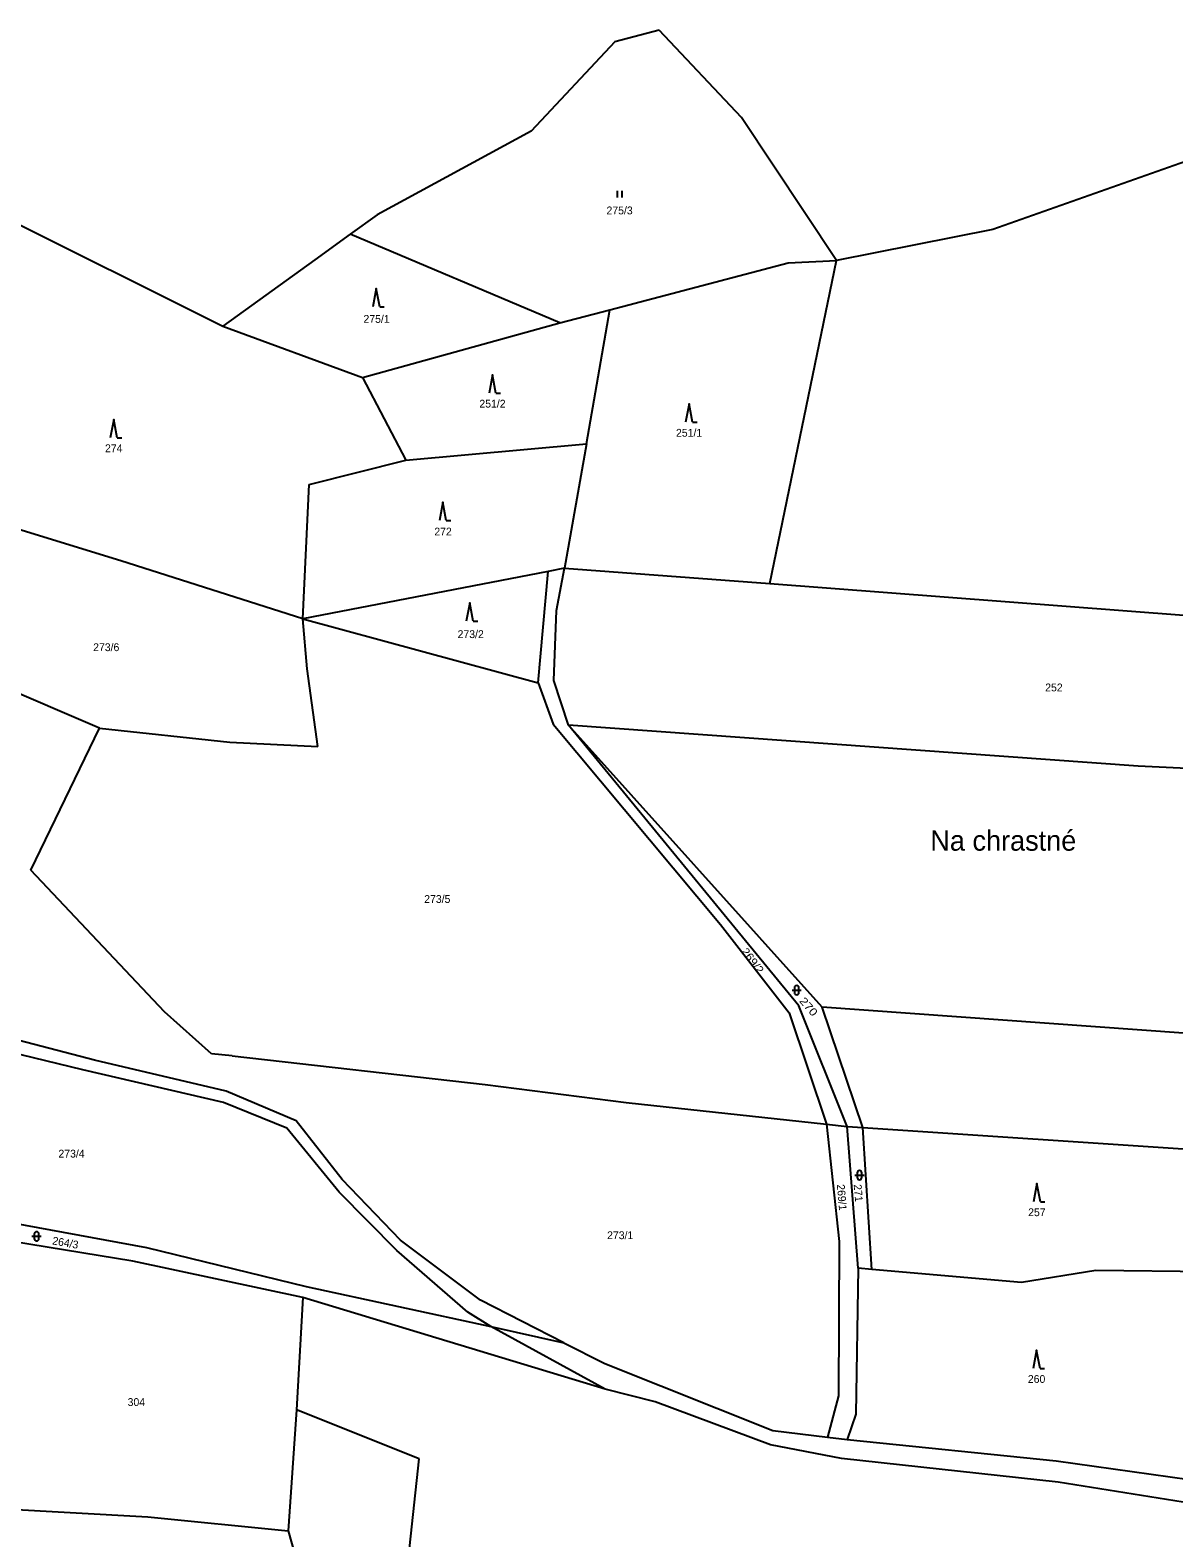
# Model space of a CAD drawing. Extents: x -791548 to -789311, y -1142631 to -1140855.
# Drawn here: x -791099.4 to -790850.9, y -1141698.3 to -1141370.5 of the extents above; entities that cross this region are included whole.
import ezdxf
from ezdxf.enums import TextEntityAlignment as Align

# ---------------------------------------------------------------- set-up
doc = ezdxf.new("R2010")
doc.units = 0
doc.header["$LTSCALE"] = 0.68
for name, color, linetype, lineweight in [('1', 7, 'Continuous', 25), ('3', 7, 'Continuous', 25), ('7', 7, 'Continuous', 13)]:
    doc.layers.add(name, color=color, linetype=linetype, lineweight=lineweight)
doc.layers.add('2', color=7, linetype='Continuous')

msp = doc.modelspace()

# ---------------------------------------------------------------- linework, layer by layer
at = {"layer": '1'}
for p, q in [((-790962.75, -1141370.54), (-790972.33, -1141373.08)), ((-790944.86, -1141389.53), (-790962.75, -1141370.54)), ((-790972.33, -1141373.08), (-790990.5, -1141392.51)), ((-790924.22, -1141420.63), (-790944.86, -1141389.53)), ((-790990.5, -1141392.51), (-791023.99, -1141410.69)), ((-790837.35, -1141395.22), (-790890.23, -1141413.86)), ((-791108.44, -1141409.5), (-791057.55, -1141434.87)), ((-791023.99, -1141410.69), (-791029.84, -1141414.9)), ((-791029.84, -1141414.9), (-791037.53, -1141420.44)), ((-790984.3, -1141434.2), (-791029.84, -1141414.9)), ((-790890.23, -1141413.86), (-790924.22, -1141420.63)), ((-791037.53, -1141420.44), (-791057.55, -1141434.87)), ((-790973.42, -1141431.36), (-790934.7, -1141421.13)), ((-790938.64, -1141490.83), (-790924.22, -1141420.63)), ((-790934.7, -1141421.13), (-790924.22, -1141420.63)), ((-790984.3, -1141434.2), (-790973.42, -1141431.36)), ((-790978.5, -1141460.45), (-790973.42, -1141431.36)), ((-791057.55, -1141434.87), (-791027.17, -1141446.05)), ((-791027.17, -1141446.05), (-790984.3, -1141434.2)), ((-791027.17, -1141446.05), (-791017.79, -1141464.03)), ((-791017.79, -1141464.03), (-790978.5, -1141460.45)), ((-790978.5, -1141460.45), (-790983.27, -1141487.53)), ((-791038.76, -1141469.32), (-791017.79, -1141464.03)), ((-791079.72, -1141485.89), (-791128.04, -1141471.09)), ((-791040.13, -1141498.5), (-791038.76, -1141469.32)), ((-791040.13, -1141498.5), (-791079.72, -1141485.89)), ((-790986.85, -1141488.22), (-791040.13, -1141498.5)), ((-790989.03, -1141512.44), (-790986.85, -1141488.22)), ((-790983.27, -1141487.53), (-790986.85, -1141488.22)), ((-790985.02, -1141496.73), (-790983.27, -1141487.53)), ((-790983.27, -1141487.53), (-790938.64, -1141490.83)), ((-790938.64, -1141490.83), (-790848.75, -1141497.75)), ((-791039.18, -1141509.38), (-791040.13, -1141498.5)), ((-791040.13, -1141498.5), (-790989.03, -1141512.44)), ((-790985.61, -1141511.92), (-790985.02, -1141496.73)), ((-791084.34, -1141522.3), (-791110.48, -1141511.03)), ((-791036.9, -1141526.25), (-791039.18, -1141509.38)), ((-790989.03, -1141512.44), (-790985.77, -1141521.43)), ((-790982.45, -1141521.64), (-790985.61, -1141511.92)), ((-790985.77, -1141521.43), (-790949.41, -1141564.98)), ((-791099.25, -1141553.12), (-791084.34, -1141522.3)), ((-791084.34, -1141522.3), (-791056.04, -1141525.31)), ((-790858.67, -1141530.56), (-790982.45, -1141521.64)), ((-790950.88, -1141560.03), (-790982.45, -1141521.64)), ((-790927.3, -1141582.95), (-790982.45, -1141521.64)), ((-791056.04, -1141525.31), (-791036.9, -1141526.25)), ((-790765.51, -1141534.95), (-790858.67, -1141530.56)), ((-791070.2, -1141583.91), (-791099.25, -1141553.12)), ((-790932.34, -1141582.61), (-790950.88, -1141560.03)), ((-790949.41, -1141564.98), (-790934.49, -1141584.17)), ((-791085.44, -1141594.43), (-791129.12, -1141583.07)), ((-790921.84, -1141608.87), (-790932.34, -1141582.61)), ((-790848.8, -1141588.58), (-790927.3, -1141582.95)), ((-790918.49, -1141609.09), (-790927.3, -1141582.95)), ((-791059.96, -1141593.07), (-791070.2, -1141583.91)), ((-790934.49, -1141584.17), (-790926.36, -1141608.38)), ((-791087.93, -1141596.55), (-791115.96, -1141589.76)), ((-791055.52, -1141593.51), (-791059.96, -1141593.07)), ((-791055.52, -1141593.51), (-791000.56, -1141599.75)), ((-791057.35, -1141603.63), (-791087.93, -1141596.55)), ((-791056.77, -1141601.17), (-791085.44, -1141594.43)), ((-791000.56, -1141599.75), (-790969.86, -1141603.69)), ((-791041.62, -1141607.64), (-791056.77, -1141601.17)), ((-791043.59, -1141609.2), (-791057.35, -1141603.63)), ((-790969.86, -1141603.69), (-790926.36, -1141608.38)), ((-791032.23, -1141623.15), (-791043.59, -1141609.2)), ((-791031.59, -1141620.42), (-791041.62, -1141607.64)), ((-790926.36, -1141608.38), (-790923.63, -1141633.86)), ((-790926.36, -1141608.38), (-790921.84, -1141608.87)), ((-790919.46, -1141639.69), (-790921.84, -1141608.87)), ((-790921.84, -1141608.87), (-790918.49, -1141609.09)), ((-790916.53, -1141639.95), (-790918.49, -1141609.09)), ((-790918.49, -1141609.09), (-790843.22, -1141614.13)), ((-791018.96, -1141633.6), (-791031.59, -1141620.42)), ((-791019.72, -1141635.8), (-791032.23, -1141623.15)), ((-791114.69, -1141627.72), (-791074.08, -1141635.2)), ((-791077.08, -1141638.15), (-791107.99, -1141633.07)), ((-791074.08, -1141635.2), (-791039.43, -1141643.64)), ((-791004.31, -1141649.23), (-791019.72, -1141635.8)), ((-791001.54, -1141646.64), (-791018.96, -1141633.6)), ((-790923.63, -1141633.86), (-790923.78, -1141667.45)), ((-791040.18, -1141646.05), (-791077.08, -1141638.15)), ((-790919.46, -1141639.69), (-790920, -1141671.39)), ((-790916.53, -1141639.95), (-790919.46, -1141639.69)), ((-790884, -1141642.79), (-790916.53, -1141639.95)), ((-790867.82, -1141640.21), (-790884, -1141642.79)), ((-790841.97, -1141640.5), (-790867.82, -1141640.21)), ((-791039.43, -1141643.64), (-790999.3, -1141652.37)), ((-791040.18, -1141646.05), (-791041.51, -1141670.46)), ((-790974.48, -1141665.95), (-791040.18, -1141646.05)), ((-790999.3, -1141652.37), (-791004.31, -1141649.23)), ((-790983.43, -1141655.93), (-791001.54, -1141646.64)), ((-790999.3, -1141652.37), (-790983.43, -1141655.93)), ((-790974.48, -1141665.95), (-790999.3, -1141652.37)), ((-790983.43, -1141655.93), (-790974.56, -1141660.37)), ((-790974.56, -1141660.37), (-790937.99, -1141674.98)), ((-790963.57, -1141668.72), (-790974.48, -1141665.95)), ((-790938.54, -1141678.09), (-790963.57, -1141668.72)), ((-790923.78, -1141667.45), (-790926.15, -1141676.4)), ((-791041.51, -1141670.46), (-791043.32, -1141696.76)), ((-791014.86, -1141681.15), (-791041.51, -1141670.46)), ((-790920, -1141671.39), (-790921.87, -1141676.88)), ((-790937.99, -1141674.98), (-790926.15, -1141676.4)), ((-790923.09, -1141681.04), (-790938.54, -1141678.09)), ((-790926.15, -1141676.4), (-790921.87, -1141676.88)), ((-790921.87, -1141676.88), (-790876.48, -1141681.58)), ((-790876, -1141686.18), (-790923.09, -1141681.04)), ((-790876.48, -1141681.58), (-790842.32, -1141686.33)), ((-790829.04, -1141693.74), (-790876, -1141686.18)), ((-791106.31, -1141691.9), (-791073.79, -1141693.75)), ((-791073.79, -1141693.75), (-791043.32, -1141696.76)), ((-791043.32, -1141696.76), (-791031.1, -1141739.78))]:
    msp.add_line(p, q, dxfattribs=at)
msp.add_lwpolyline([(-790970.9, -1141745.32), (-791021.42, -1141741.6), (-791014.86, -1141681.15)], dxfattribs=at)
at = {"layer": '3'}
for p, q in [((-790971.781, -1141406.94), (-790971.781, -1141405.44)), ((-790970.78, -1141406.94), (-790970.78, -1141405.44)), ((-791023.44, -1141430.71), (-791022.444, -1141430.71)), ((-790998.19, -1141449.46), (-790997.194, -1141449.46)), ((-790955.47, -1141455.79), (-790954.474, -1141455.79)), ((-791080.48, -1141459.15), (-791079.484, -1141459.15)), ((-791008.98, -1141477.12), (-791007.984, -1141477.12)), ((-791003.14, -1141499.04), (-791002.144, -1141499.04)), ((-790933.841, -1141579.241), (-790931.839, -1141579.241)), ((-790933.341, -1141578.741), (-790933.341, -1141579.742)), ((-790932.339, -1141579.742), (-790932.339, -1141578.741)), ((-790920.191, -1141619.441), (-790918.189, -1141619.441)), ((-790919.691, -1141618.941), (-790919.691, -1141619.942)), ((-790918.689, -1141619.942), (-790918.689, -1141618.941)), ((-790879.9, -1141625.23), (-790878.904, -1141625.23)), ((-791099.001, -1141632.741), (-791096.999, -1141632.741)), ((-791098.501, -1141632.241), (-791098.501, -1141633.242)), ((-791097.499, -1141633.242), (-791097.499, -1141632.241)), ((-790879.97, -1141661.48), (-790878.974, -1141661.48))]:
    msp.add_line(p, q, dxfattribs=at)
for points in [[(-791023.44, -1141430.71), (-791024.19, -1141426.71), (-791024.94, -1141430.71)], [(-790998.19, -1141449.46), (-790998.94, -1141445.46), (-790999.69, -1141449.46)], [(-790955.47, -1141455.79), (-790956.22, -1141451.79), (-790956.97, -1141455.79)], [(-791080.48, -1141459.15), (-791081.23, -1141455.15), (-791081.98, -1141459.15)], [(-791008.98, -1141477.12), (-791009.73, -1141473.12), (-791010.48, -1141477.12)], [(-791003.14, -1141499.04), (-791003.89, -1141495.04), (-791004.64, -1141499.04)], [(-790879.9, -1141625.23), (-790880.65, -1141621.23), (-790881.4, -1141625.23)], [(-790879.97, -1141661.48), (-790880.72, -1141657.48), (-790881.47, -1141661.48)]]:
    msp.add_lwpolyline(points, dxfattribs=at)
for centre, start, end in [((-790932.84, -1141578.7409), 0, 180), ((-790932.84, -1141579.7409), 180, 359.98789), ((-790919.19, -1141618.9409), 0, 180), ((-790919.19, -1141619.9409), 180, 359.98789), ((-791098, -1141632.2409), 0, 180), ((-791098, -1141633.2409), 180, 359.98789)]:
    msp.add_arc(centre, 0.5, start, end, dxfattribs=at)

# ---------------------------------------------------------------- texts
at = {"layer": '2'}
for s, p in [('275/3', (-790971.32, -1141410.582)), ('275/1', (-791024.12, -1141434.162)), ('251/2', (-790998.94, -1141452.592)), ('251/1', (-790956.22, -1141458.922)), ('274', (-791081.229, -1141462.282)), ('272', (-791009.679, -1141480.392)), ('273/2', (-791003.67, -1141502.692)), ('273/6', (-791082.86, -1141505.532)), ('252', (-790876.949, -1141514.282)), ('273/5', (-791010.93, -1141560.272)), ('273/4', (-791090.4, -1141615.622)), ('257', (-790880.649, -1141628.362)), ('273/1', (-790971.19, -1141633.362)), ('260', (-790880.719, -1141664.612)), ('304', (-791076.319, -1141669.622))]:
    msp.add_text(s, height=1.7, dxfattribs=at).set_placement(p, align=Align.CENTER)
for s, rotation, width, p in [('269/2', 307, 1.1, (-790943.0879, -1141573.3315)), ('270', 311, 1.2, (-790930.8903, -1141583.3754))]:
    msp.add_text(s, height=1.7, rotation=rotation, dxfattribs=dict(at, width=width)).set_placement(p, align=Align.CENTER)
for s, rotation, p in [('269/1', 275, (-790923.8695, -1141624.3439)), ('271', 275, (-790920.2899, -1141623.4044)), ('264/3', 350, (-791091.8766, -1141634.9758))]:
    msp.add_text(s, height=1.7, rotation=rotation, dxfattribs=at).set_placement(p, align=Align.CENTER)
at = {"layer": '7'}
msp.add_text('Na chrastné', height=4.4, dxfattribs=at).set_placement((-790903.81, -1141548.92))

doc.saveas('drawing.dxf')
